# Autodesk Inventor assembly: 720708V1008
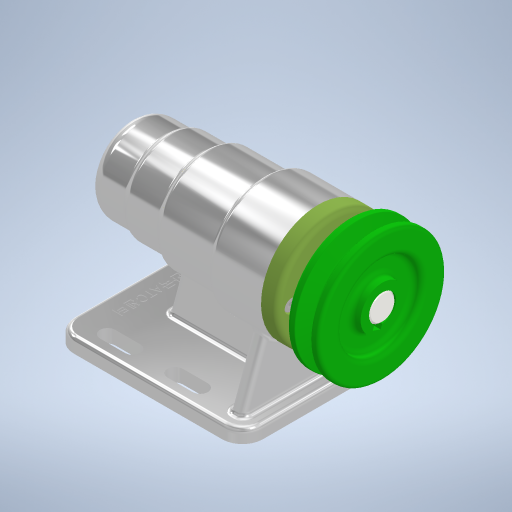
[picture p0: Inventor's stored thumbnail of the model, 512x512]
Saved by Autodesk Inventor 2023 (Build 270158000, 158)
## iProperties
Created: 2022-07
Part Number: 720708V1008
Document SubType Name: Assembly
Designer: owner
Author: owner
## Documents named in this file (12)
- C:\Users\owner\Desktop\720708V1008\720708V1008.iam
- C:\Users\owner\Desktop\720708V1008\본체.ipt
- C:\Users\owner\Desktop\720708V1008\V벨트풀리.ipt
- C:\Users\owner\Desktop\720708V1008\멈춤나사 M3.ipt
- C:\Users\owner\Desktop\720708V1008\베어링 6004.ipt
- C:\Users\owner\Desktop\720708V1008\베어링 51202.ipt
- C:\Users\owner\Desktop\720708V1008\볼트 M4.ipt
- C:\Users\owner\Desktop\720708V1008\어댑터슬리브.ipt
- C:\Users\owner\Desktop\720708V1008\오일 실 20x35x7.ipt
- C:\Users\owner\Desktop\720708V1008\축.ipt
- C:\Users\owner\Desktop\720708V1008\커버.ipt
- C:\Users\owner\Desktop\720708V1008\키 5x5.ipt
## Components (1 placed, 1 different names)
1. V벨트풀리:1 — 강체:8
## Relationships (1: WeldJoint 1)
- 강체:8 [WeldJoint]: V벨트풀리:1
